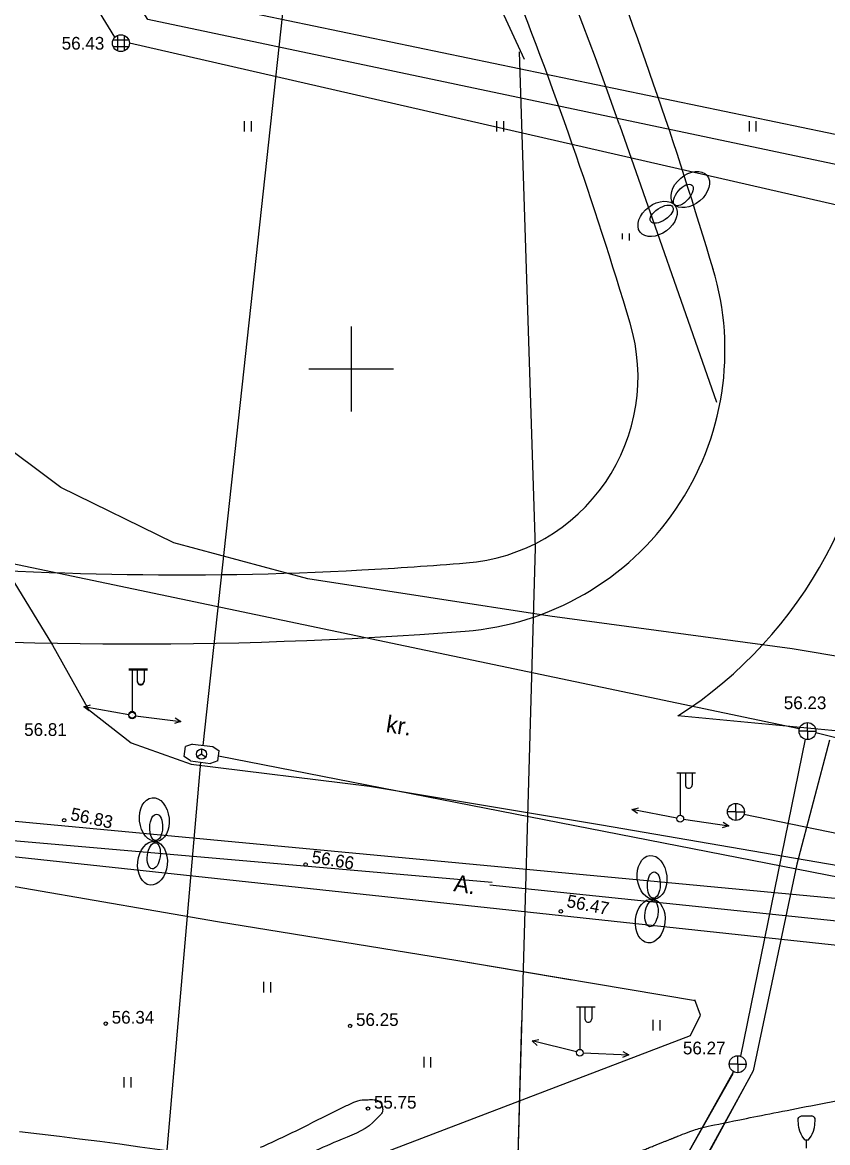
# Model space of a CAD drawing. Extents: x 9156 to 9809, y 2728 to 4000.
# Drawn here: x 9430.6 to 9478.1, y 3704.4 to 3770.4 of the extents above; entities that cross this region are included whole.
import ezdxf

# ---------------------------------------------------------------- set-up
doc = ezdxf.new("R2010")
doc.units = 0
for name, color, linetype in [('Level 12', 7, 'Continuous'), ('Level 16', 7, 'Continuous'), ('Level 17', 7, 'Continuous'), ('Level 18', 7, 'Continuous'), ('Level 54', 7, 'Continuous'), ('Level 56', 7, 'Continuous'), ('Level 8', 7, 'Continuous')]:
    doc.layers.add(name, color=color, linetype=linetype)

msp = doc.modelspace()

# ---------------------------------------------------------------- linework, layer by layer
at = {"layer": 'Level 12'}
for p, q in [((9460.217, 3768.222), (9442.699, 3806.141)), ((9460.856, 3739.471), (9459.915, 3768.675)), ((9459.613, 3695.388), (9460.856, 3739.471)), ((9460.029, 3711.631), (9459.613, 3695.388))]:
    msp.add_line(p, q, dxfattribs=at)
at = {"layer": 'Level 16'}
for p, q in [((9362.36, 3728.08), (9458.317, 3719.771)), ((9458.166, 3719.62), (9482.782, 3717.052))]:
    msp.add_line(p, q, dxfattribs=at)
at = {"layer": 'Level 17'}
msp.add_line((9465.812, 3764.381), (9471.526, 3748.04), dxfattribs=at)
for centre, radius, start, end in [((9232.654, 3682.856), 247, 19.27262, 27.05047), ((9232.654, 3682.856), 244, 16.63018, 27.05044), ((9455.908, 3749.539), 11, 274.52895, 16.63018), ((9439.835, 3937.872), 200, 264.63885, 273.09432), ((9437.352, 3983.805), 246, 273.09432, 274.52895)]:
    msp.add_arc(centre, radius, start, end, dxfattribs=at)
at = {"layer": 'Level 18'}
for p, q in [((9486.214, 3718.077), (9323.495, 3733.347)), ((9492.797, 3727.352), (9469.262, 3729.561)), ((9485.854, 3715.259), (9390.755, 3725.475))]:
    msp.add_line(p, q, dxfattribs=at)
for centre, radius, start, end in [((9231.641, 3684.839), 250, 16.49447, 27.05049), ((9455.436, 3751.106), 16.6, 274.44386, 16.82171), ((9455.436, 3751.106), 25.6, 302.68899, 0.88319), ((9437.352, 3983.805), 250, 264.63885, 274.44386), ((9402.629, 3456.616), 250, 74.8696, 83.61425)]:
    msp.add_arc(centre, radius, start, end, dxfattribs=at)
at = {"layer": 'Level 54'}
for p, q in [((9436.069, 3769.543), (9427.903, 3782.805)), ((9440.222, 3771.81), (9481.12, 3763.279)), ((9436.222, 3769.648), (9436.222, 3768.731)), ((9436.622, 3769.648), (9436.622, 3768.731)), ((9435.964, 3769.389), (9436.88, 3769.389)), ((9435.964, 3768.989), (9436.88, 3768.989)), ((9480.363, 3759.245), (9436.922, 3769.189)), ((9443.692, 3764.605), (9443.692, 3763.985)), ((9444.098, 3764.594), (9444.098, 3763.985)), ((9458.574, 3764.605), (9458.574, 3763.985)), ((9458.98, 3764.594), (9458.98, 3763.985)), ((9473.456, 3764.605), (9473.456, 3763.985)), ((9473.861, 3764.594), (9473.861, 3763.985)), ((9465.98, 3757.985), (9465.98, 3757.641)), ((9466.385, 3757.974), (9466.385, 3757.573)), ((9450, 3752.5), (9450, 3747.5)), ((9447.5, 3750), (9452.5, 3750)), ((9447.5, 3750), (9452.5, 3750)), ((9447.5, 3750), (9452.5, 3750)), ((9447.5, 3750), (9452.5, 3750)), ((9450, 3750), (9450, 3747.5)), ((9450, 3750), (9450, 3747.5)), ((9450, 3750), (9450, 3747.5)), ((9432.871, 3743.025), (9432.871, 3743.025)), ((9432.871, 3743.025), (9432.871, 3743.025)), ((9439.536, 3739.756), (9439.536, 3739.756)), ((9439.536, 3739.756), (9439.536, 3739.756)), ((9447.448, 3737.643), (9447.448, 3737.643)), ((9461.709, 3735.442), (9461.709, 3735.442)), ((9461.709, 3735.442), (9461.709, 3735.442)), ((9432.397, 3733.729), (9432.397, 3733.729)), ((9432.397, 3733.729), (9432.397, 3733.729)), ((9475.986, 3733.512), (9475.986, 3733.512)), ((9436.885, 3732.286), (9437.985, 3732.286)), ((9436.887, 3732.33), (9437.987, 3732.33)), ((9437.085, 3732.286), (9437.085, 3729.786)), ((9437.087, 3732.33), (9437.087, 3729.83)), ((9437.385, 3732.286), (9437.385, 3731.586)), ((9437.387, 3732.33), (9437.387, 3731.63)), ((9437.785, 3732.286), (9437.785, 3731.586)), ((9437.787, 3732.33), (9437.787, 3731.63)), ((9434.513, 3729.945), (9434.513, 3729.945)), ((9434.513, 3729.945), (9434.513, 3729.945)), ((9437.085, 3729.586), (9437.085, 3729.586)), ((9437.087, 3729.63), (9437.087, 3729.63)), ((9476.899, 3728.672), (9476.399, 3728.672)), ((9476.89, 3728.664), (9476.89, 3728.664)), ((9476.899, 3728.672), (9476.899, 3729.172)), ((9476.899, 3728.672), (9476.899, 3728.672)), ((9476.899, 3728.672), (9477.399, 3728.672)), ((9476.899, 3728.672), (9476.899, 3728.172)), ((9472.959, 3709.517), (9476.785, 3728.185)), ((9478.203, 3728.133), (9476.261, 3720.822)), ((9437.034, 3727.973), (9437.034, 3727.973)), ((9437.034, 3727.973), (9437.034, 3727.973)), ((9440.148, 3727.165), (9440.224, 3727.76)), ((9440.148, 3727.165), (9440.224, 3727.76)), ((9440.646, 3727.907), (9440.224, 3727.76)), ((9440.646, 3727.907), (9440.224, 3727.76)), ((9440.646, 3727.907), (9441.836, 3727.755)), ((9440.646, 3727.907), (9441.836, 3727.755)), ((9441.175, 3727.615), (9441.175, 3727.315)), ((9441.175, 3727.615), (9441.175, 3727.315)), ((9441.836, 3727.755), (9442.208, 3727.505)), ((9441.836, 3727.755), (9442.208, 3727.505)), ((9442.131, 3726.91), (9442.208, 3727.505)), ((9442.131, 3726.91), (9442.208, 3727.505)), ((9440.519, 3726.916), (9440.148, 3727.165)), ((9440.519, 3726.916), (9440.148, 3727.165)), ((9440.519, 3726.916), (9441.709, 3726.763)), ((9440.519, 3726.916), (9441.709, 3726.763)), ((9440.569, 3726.721), (9440.569, 3726.721)), ((9440.569, 3726.721), (9440.569, 3726.721)), ((9441.175, 3727.315), (9440.925, 3727.149)), ((9441.175, 3727.315), (9440.925, 3727.149)), ((9441.175, 3727.315), (9441.175, 3727.315)), ((9441.175, 3727.315), (9441.425, 3727.149)), ((9441.175, 3727.315), (9441.175, 3727.315)), ((9441.175, 3727.315), (9441.425, 3727.149)), ((9442.131, 3726.91), (9441.709, 3726.763)), ((9442.131, 3726.91), (9441.709, 3726.763)), ((9469.197, 3726.209), (9470.297, 3726.209)), ((9469.397, 3726.209), (9469.397, 3723.709)), ((9469.697, 3726.209), (9469.697, 3725.509)), ((9470.097, 3726.209), (9470.097, 3725.509)), ((9451.079, 3725.424), (9451.079, 3725.424)), ((9451.079, 3725.424), (9451.079, 3725.424)), ((9472.68, 3723.91), (9472.68, 3724.41)), ((9433.077, 3723.419), (9433.077, 3723.419)), ((9469.397, 3723.509), (9469.397, 3723.509)), ((9469.46, 3723.535), (9469.46, 3723.535)), ((9472.68, 3723.91), (9472.18, 3723.91)), ((9472.68, 3723.956), (9472.68, 3723.956)), ((9472.68, 3723.91), (9473.18, 3723.91)), ((9472.68, 3723.91), (9472.68, 3723.41)), ((9472.693, 3723.974), (9472.693, 3723.974)), ((9464.755, 3723.151), (9464.755, 3723.151)), ((9447.31, 3720.811), (9447.31, 3720.811)), ((9476.261, 3720.822), (9473.693, 3708.659)), ((9476.261, 3720.822), (9476.261, 3720.822)), ((9462.356, 3718.051), (9462.356, 3718.051)), ((9442.117, 3717.437), (9442.117, 3717.437)), ((9442.117, 3717.437), (9442.117, 3717.437)), ((9456.282, 3715.131), (9456.282, 3715.131)), ((9456.282, 3715.131), (9456.282, 3715.131)), ((9444.83, 3713.9), (9444.83, 3713.28)), ((9445.235, 3713.889), (9445.235, 3713.28)), ((9470.248, 3712.831), (9470.248, 3712.831)), ((9463.275, 3712.423), (9464.375, 3712.423)), ((9463.475, 3712.423), (9463.475, 3709.923)), ((9463.775, 3712.423), (9463.775, 3711.723)), ((9464.175, 3712.423), (9464.175, 3711.723)), ((9470.303, 3712.785), (9470.303, 3712.785)), ((9467.78, 3711.653), (9467.78, 3711.033)), ((9468.186, 3711.642), (9468.186, 3711.033)), ((9470.598, 3711.934), (9470.598, 3711.934)), ((9435.531, 3711.436), (9435.531, 3711.436)), ((9449.933, 3711.302), (9449.933, 3711.302)), ((9470.01, 3710.742), (9470.01, 3710.742)), ((9463.475, 3709.723), (9463.475, 3709.723)), ((9472.782, 3709.049), (9472.782, 3709.549)), ((9454.271, 3709.477), (9454.271, 3708.857)), ((9454.677, 3709.466), (9454.677, 3708.857)), ((9472.782, 3709.049), (9472.282, 3709.049)), ((9472.753, 3709.06), (9472.753, 3709.06)), ((9472.782, 3709.049), (9472.782, 3709.049)), ((9472.782, 3709.049), (9473.282, 3709.049)), ((9472.782, 3709.049), (9472.782, 3708.549)), ((9436.603, 3708.288), (9436.603, 3707.668)), ((9437.009, 3708.277), (9437.009, 3707.668)), ((9463.159, 3691.857), (9472.53, 3708.596)), ((9473.693, 3708.659), (9463.896, 3690.683)), ((9473.693, 3708.659), (9473.693, 3708.659)), ((9450.988, 3706.432), (9450.988, 3706.432)), ((9476.548, 3705.998), (9477.148, 3705.998)), ((9476.748, 3704.598), (9476.948, 3704.598)), ((9476.848, 3704.098), (9476.848, 3704.598))]:
    msp.add_line(p, q, dxfattribs=at)
for points in [[(9449.915, 3807.396), (9441.243, 3727.823)], [(9481.999, 3761.308), (9438.003, 3770.592), (9429.016, 3784.957)], [(9489.602, 3731.233), (9475.986, 3733.512), (9461.709, 3735.442), (9447.448, 3737.643), (9439.536, 3739.756), (9432.871, 3743.025), (9428.787, 3746.065), (9424.715, 3750)], [(9416.737, 3741.325), (9476.415, 3728.821)], [(9430.118, 3737.47), (9432.397, 3733.729), (9434.513, 3729.945), (9437.034, 3727.973), (9440.569, 3726.721), (9451.079, 3725.424), (9464.755, 3723.151), (9479.973, 3720.53), (9493.795, 3717.996)], [(9434.558, 3729.866), (9434.232, 3730.105), (9434.627, 3730.212)], [(9436.888, 3729.622), (9434.232, 3730.105)], [(9437.284, 3729.562), (9439.964, 3729.24)], [(9439.624, 3729.458), (9439.964, 3729.24), (9439.577, 3729.109)], [(9477.385, 3728.593), (9499.824, 3722.986)], [(9441.114, 3726.839), (9437.637, 3686.762)], [(9442.17, 3727.208), (9499.879, 3715.934)], [(9466.873, 3723.813), (9466.549, 3724.054), (9466.945, 3724.158)], [(9469.201, 3723.546), (9466.549, 3724.054)], [(9470.303, 3712.785), (9456.282, 3715.131), (9442.117, 3717.437), (9427.547, 3719.95), (9413.66, 3722.187), (9402.728, 3723.584), (9400.913, 3722.502), (9399.5, 3721.043), (9399.457, 3709.921), (9399.588, 3699.638)], [(9463.006, 3714.006), (9456.282, 3715.131), (9442.117, 3717.437), (9427.547, 3719.95), (9413.66, 3722.187), (9402.728, 3723.584), (9400.913, 3722.502), (9399.5, 3721.043), (9399.47, 3713.346)], [(9469.593, 3723.472), (9472.266, 3723.086)], [(9473.149, 3723.769), (9500, 3718.257)], [(9471.931, 3723.313), (9472.266, 3723.086), (9471.875, 3722.965)], [(9399.579, 3691.208), (9399.669, 3684.552), (9404.608, 3688.59), (9408.655, 3690.933), (9415.413, 3693.131), (9426.596, 3695.582), (9439.668, 3699.157), (9470.01, 3710.742), (9470.598, 3711.934), (9470.248, 3712.831)], [(9460.971, 3710.159), (9460.659, 3710.417), (9461.06, 3710.5)], [(9463.281, 3709.771), (9460.659, 3710.417)], [(9463.675, 3709.715), (9466.373, 3709.605)], [(9466.016, 3709.796), (9466.373, 3709.605), (9465.997, 3709.444)], [(9463.241, 3692.109), (9472.51, 3708.506)], [(9463.915, 3690.842), (9473.564, 3708.379)], [(9476.748, 3704.598), (9476.59, 3704.811), (9476.525, 3704.923), (9476.448, 3705.098), (9476.387, 3705.323), (9476.363, 3705.479), (9476.348, 3705.798), (9476.35, 3705.84), (9476.38, 3705.911), (9476.42, 3705.948), (9476.548, 3705.998)], [(9476.948, 3704.598), (9477.106, 3704.811), (9477.171, 3704.923), (9477.248, 3705.098), (9477.309, 3705.323), (9477.333, 3705.479), (9477.348, 3705.798), (9477.346, 3705.84), (9477.316, 3705.911), (9477.276, 3705.948), (9477.148, 3705.998)]]:
    msp.add_lwpolyline(points, dxfattribs=at)
for centre, radius in [((9436.422, 3769.189), 0.5), ((9437.085, 3729.586), 0.2), ((9437.087, 3729.63), 0.2), ((9476.899, 3728.672), 0.5), ((9441.175, 3727.315), 0.3), ((9441.175, 3727.315), 0.3), ((9472.68, 3723.91), 0.5), ((9433.077, 3723.419), 0.1), ((9469.397, 3723.509), 0.2), ((9447.31, 3720.811), 0.1), ((9462.356, 3718.051), 0.1), ((9435.531, 3711.436), 0.1), ((9449.933, 3711.302), 0.1), ((9463.475, 3709.723), 0.2), ((9472.782, 3709.049), 0.5), ((9450.988, 3706.432), 0.1)]:
    msp.add_circle(centre, radius, dxfattribs=at)
for centre in [(9437.585, 3731.586), (9437.587, 3731.63), (9469.897, 3725.509), (9463.975, 3711.723)]:
    msp.add_arc(centre, 0.2, 179.93931, 0.0607, dxfattribs=at)
msp.add_open_spline([(9456.036, 3699.596), (9459.877, 3701.043), (9462.13, 3701.966), (9465.816, 3703.444), (9468.745, 3704.598), (9470.032, 3705.126), (9471.191, 3705.455), (9484.079, 3707.958), (9487.812, 3708.551), (9490.419, 3708.749), (9495.812, 3709.078), (9498.129, 3709.078), (9499.964, 3708.913)], degree=2, dxfattribs=at)
msp.add_spline([(9444.661, 3704.152), (9447.182, 3705.342), (9449.415, 3706.464), (9450.028, 3706.748), (9450.524, 3706.928), (9450.991, 3706.958), (9451.355, 3706.958), (9451.706, 3706.808), (9451.852, 3706.434), (9451.822, 3706.195), (9451.676, 3706.015), (9451.282, 3705.611), (9449.196, 3704.52), (9445.937, 3702.939)], degree=3, dxfattribs=at)
at = {"layer": 'Level 56'}
for p, q in [((9465.812, 3764.381), (9471.526, 3748.04)), ((9486.214, 3718.077), (9323.495, 3733.347)), ((9492.797, 3727.352), (9469.262, 3729.561)), ((9485.854, 3715.259), (9390.755, 3725.475))]:
    msp.add_line(p, q, dxfattribs=at)
for centre, radius, start, end in [((9231.641, 3684.839), 250, 16.49447, 27.05049), ((9232.654, 3682.856), 247, 19.27262, 27.05047), ((9232.654, 3682.856), 244, 16.63018, 27.05044), ((9455.436, 3751.106), 16.6, 274.44386, 16.82171), ((9455.908, 3749.539), 11, 274.52895, 16.63018), ((9455.436, 3751.106), 25.6, 302.68899, 0.88319), ((9439.835, 3937.872), 200, 264.63885, 273.09432), ((9437.352, 3983.805), 246, 273.09432, 274.52895), ((9437.352, 3983.805), 250, 264.63885, 274.44386), ((9402.629, 3456.616), 250, 74.8696, 83.61425)]:
    msp.add_arc(centre, radius, start, end, dxfattribs=at)
at = {"layer": 'Level 8'}
for centre, major_axis, ratio in [((9469.988, 3760.568), (-0.986, -0.837), 0.674652), ((9469.988, 3760.568), (-0.986, -0.837), 0.674652), ((9469.988, 3760.568), (-0.986, -0.837), 0.674652), ((9469.988, 3760.568), (-0.986, -0.837), 0.674652), ((9469.576, 3760.245), (-0.507, -0.589), 0.486914), ((9469.576, 3760.245), (-0.507, -0.589), 0.486914), ((9469.576, 3760.245), (-0.507, -0.589), 0.486914), ((9469.576, 3760.245), (-0.507, -0.589), 0.486914), ((9468.064, 3758.838), (1.034, 0.776), 0.674652), ((9468.064, 3758.838), (1.034, 0.776), 0.674652), ((9468.064, 3758.838), (1.034, 0.776), 0.674652), ((9468.064, 3758.838), (1.034, 0.776), 0.674652), ((9468.304, 3759.116), (0.646, 0.434), 0.486914), ((9468.304, 3759.116), (0.646, 0.434), 0.486914), ((9468.304, 3759.116), (0.646, 0.434), 0.486914), ((9468.304, 3759.116), (0.646, 0.434), 0.486914), ((9438.393, 3723.455), (0.134, -1.286), 0.674652), ((9438.393, 3723.455), (0.134, -1.286), 0.674652), ((9438.393, 3723.455), (0.134, -1.286), 0.674652), ((9438.393, 3723.455), (0.134, -1.286), 0.674652), ((9438.5, 3723), (-0.027, -0.777), 0.486914), ((9438.5, 3723), (-0.027, -0.777), 0.486914), ((9438.5, 3723), (-0.027, -0.777), 0.486914), ((9438.5, 3723), (-0.027, -0.777), 0.486914), ((9438.286, 3720.883), (0.134, 1.286), 0.674652), ((9438.286, 3720.883), (0.134, 1.286), 0.674652), ((9438.286, 3720.883), (0.134, 1.286), 0.674652), ((9438.286, 3720.883), (0.134, 1.286), 0.674652), ((9438.359, 3721.319), (0.102, 0.771), 0.486914), ((9438.359, 3721.319), (0.102, 0.771), 0.486914), ((9438.359, 3721.319), (0.102, 0.771), 0.486914), ((9438.359, 3721.319), (0.102, 0.771), 0.486914), ((9467.734, 3720.053), (0.134, -1.286), 0.674652), ((9467.734, 3720.053), (0.134, -1.286), 0.674652), ((9467.734, 3720.053), (0.134, -1.286), 0.674652), ((9467.734, 3720.053), (0.134, -1.286), 0.674652), ((9467.841, 3719.598), (-0.027, -0.777), 0.486914), ((9467.841, 3719.598), (-0.027, -0.777), 0.486914), ((9467.841, 3719.598), (-0.027, -0.777), 0.486914), ((9467.841, 3719.598), (-0.027, -0.777), 0.486914), ((9467.627, 3717.481), (0.134, 1.286), 0.674652), ((9467.627, 3717.481), (0.134, 1.286), 0.674652), ((9467.627, 3717.481), (0.134, 1.286), 0.674652), ((9467.627, 3717.481), (0.134, 1.286), 0.674652), ((9467.7, 3717.917), (0.102, 0.771), 0.486914), ((9467.7, 3717.917), (0.102, 0.771), 0.486914), ((9467.7, 3717.917), (0.102, 0.771), 0.486914), ((9467.7, 3717.917), (0.102, 0.771), 0.486914)]:
    msp.add_ellipse(centre, major_axis=major_axis, ratio=ratio, dxfattribs=at)

# ---------------------------------------------------------------- texts
at = {"layer": 'Level 54'}
for s, p in [('56.43', (9432.933, 3768.808)), ('56.23', (9475.501, 3729.961)), ('56.81', (9430.719, 3728.385)), ('56.34', (9435.881, 3711.436)), ('56.25', (9450.283, 3711.302)), ('56.27', (9469.555, 3709.627)), ('55.75', (9451.338, 3706.432))]:
    msp.add_text(s, height=0.75, dxfattribs=at).set_placement(p)
for s, height, rotation, p in [('kr.', 1, 351.22637, (9452.008, 3728.615)), ('56.83', 0.75, 347.90612, (9433.401, 3723.444)), ('56.66', 0.75, 350.90295, (9447.627, 3720.907)), ('A.', 1, 350.75361, (9455.997, 3719.248)), ('56.47', 0.75, 348.78125, (9462.655, 3718.318))]:
    msp.add_text(s, height=height, rotation=rotation, dxfattribs=at).set_placement(p)

doc.saveas('drawing.dxf')
